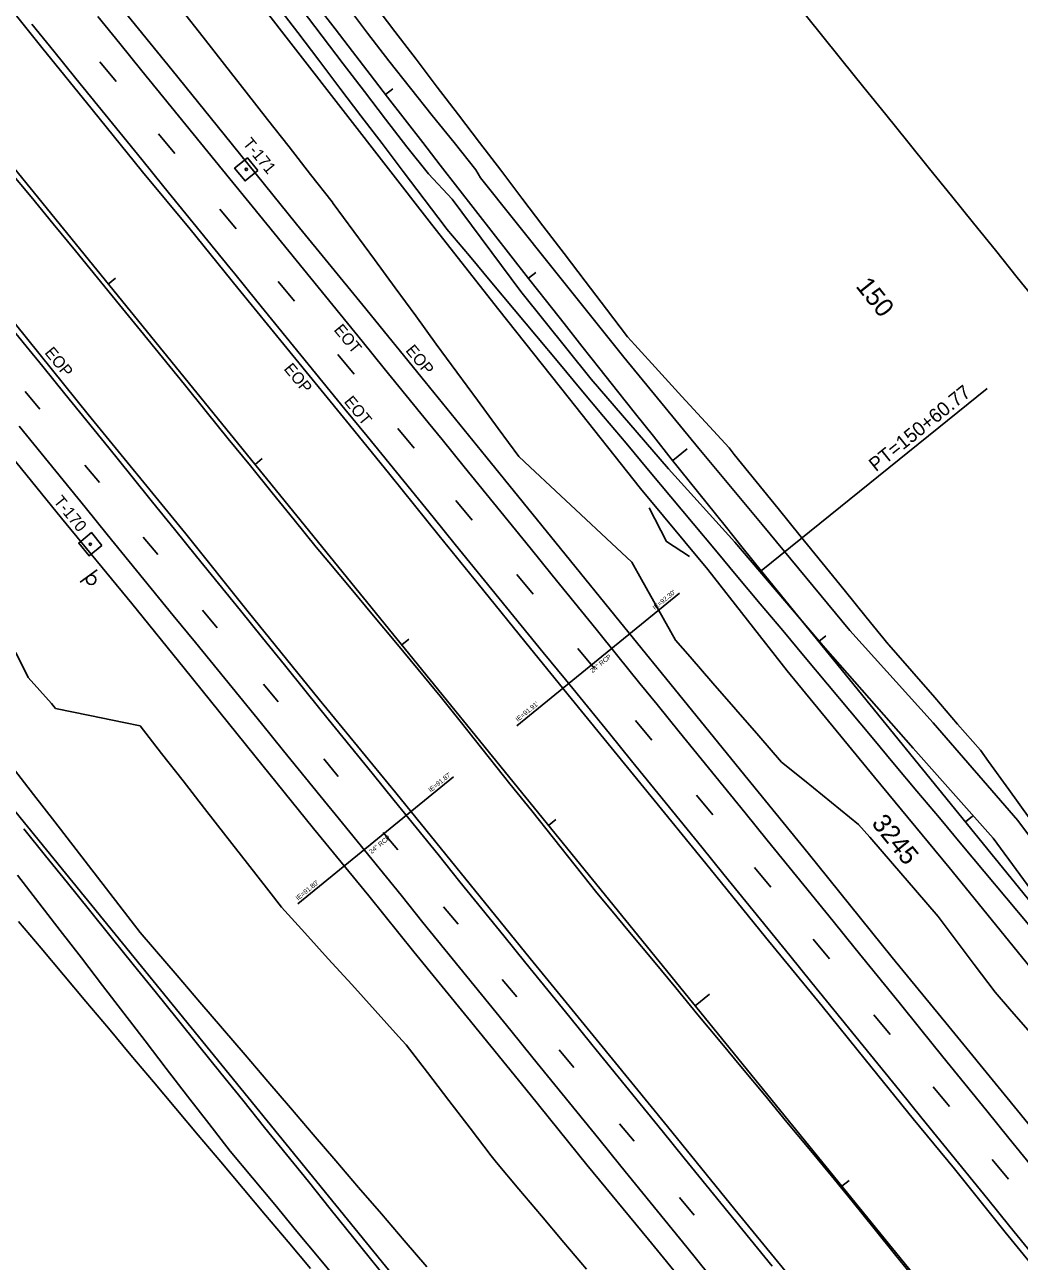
# Model space of a CAD drawing. Extents: x 2132221 to 2141942, y 535736 to 547298.
# Drawn here: x 2140262 to 2140690, y 537530 to 538062 of the extents above; entities that cross this region are included whole.
import ezdxf

# ---------------------------------------------------------------- set-up
doc = ezdxf.new("R2010")
doc.units = 0
for name, color, linetype in [('RD_EX_BldgApp', 7, 'Continuous'), ('RD_EX_DR_Inlet_txCode', 7, 'Continuous'), ('RD_EX_DR_Pipe', 7, 'Continuous'), ('RD_EX_DR_Pipe_txCode', 7, 'Continuous'), ('RD_EX_Driveway', 7, 'Continuous'), ('RD_EX_Fence_Other', 7, 'Continuous'), ('RD_EX_GuardRail', 7, 'Continuous'), ('RD_EX_Misc', 7, 'Continuous'), ('RD_EX_Misc_txCode', 7, 'Continuous'), ('RD_EX_Road', 7, 'Continuous'), ('RD_EX_Road_txCode', 7, 'Continuous'), ('RD_EX_VEG', 7, 'Continuous'), ('RD_HC_Cl', 7, 'Continuous'), ('RD_HC_Data', 7, 'Continuous'), ('RD_HC_Data_Tic', 7, 'Continuous'), ('RD_HC_Survey', 7, 'Continuous'), ('RD_HC_Survey_txCode', 7, 'Continuous'), ('RD_HC_TX_Sta50', 7, 'Continuous'), ('TOPO_E_TLIML-Line', 7, 'Continuous')]:
    doc.layers.add(name, color=color, linetype=linetype)

msp = doc.modelspace()

# ---------------------------------------------------------------- linework, layer by layer
at = {"layer": 'RD_EX_BldgApp'}
msp.add_line((2140293.26, 537827.39), (2140285.95, 537822.14), dxfattribs=at)
msp.add_circle((2140290.77, 537823.11), 2, dxfattribs=at)
at = {"layer": 'RD_EX_DR_Pipe'}
for points in [[(2140473.68, 537760.27), (2140543.61, 537817.28)], [(2140446.58, 537738.36), (2140379.58, 537683.77)]]:
    msp.add_lwpolyline(points, dxfattribs=at)
at = {"layer": 'RD_EX_Driveway'}
for points in [[(2140380.95, 538068.73), (2140390.03, 538056.84), (2140399.12, 538044.94), (2140408.21, 538033.05), (2140417.29, 538021.16), (2140426.45, 538009.32), (2140435.8, 537997.63), (2140445.93, 537986.7)], [(2140458.06, 537995.95), (2140456.14, 537999.39), (2140446.75, 538011.09), (2140437.36, 538022.79), (2140427.97, 538034.48), (2140418.66, 538046.24), (2140409.58, 538058.18), (2140400.51, 538070.13)], [(2140458.06, 537995.95), (2140488.23, 537958.18), (2140519.81, 537918.83), (2140552.04, 537879.57), (2140579.22, 537846.81), (2140616.97, 537801.32), (2140652.79, 537761.62), (2140689.12, 537719.55), (2140720.75, 537677.36)], [(2140445.93, 537986.7), (2140475.53, 537947), (2140505.71, 537909.4), (2140538.89, 537870.87), (2140567.54, 537839.33), (2140606.35, 537793.62), (2140644.19, 537750.74), (2140678.5, 537711.95), (2140709.72, 537669.37)], [(2140261.73, 537716.06), (2140271.14, 537704.38), (2140280.56, 537692.71), (2140289.98, 537681.03), (2140299.39, 537669.36), (2140308.81, 537657.68), (2140318.22, 537646.01), (2140327.64, 537634.34), (2140337.05, 537622.66), (2140346.47, 537610.99), (2140355.89, 537599.31), (2140365.3, 537587.64), (2140384.13, 537564.29), (2140393.55, 537552.62), (2140431.21, 537505.92)], [(2140398.38, 537519.84), (2140388.8, 537531.36), (2140379.22, 537542.87), (2140369.64, 537554.39), (2140360.06, 537565.9), (2140350.49, 537577.42), (2140341.27, 537589.22), (2140332.14, 537601.1), (2140323.02, 537612.97), (2140313.89, 537624.85), (2140304.76, 537636.72), (2140295.63, 537648.6), (2140286.5, 537660.47), (2140277.37, 537672.35), (2140268.25, 537684.22), (2140259.12, 537696.1)]]:
    msp.add_lwpolyline(points, dxfattribs=at)
at = {"layer": 'RD_EX_Fence_Other'}
for p, q in [((2140437.03, 537975.97), (2140347.96, 538090.82)), ((2140167.14, 537835.13), (2140668.17, 537219.94))]:
    msp.add_line(p, q, dxfattribs=at)
msp.add_lwpolyline([(2140437.03, 537975.97), (2140466.04, 537939.25), (2140495.76, 537901.58), (2140526.85, 537862.32), (2140555.79, 537827.47), (2140590, 537783.88), (2140627.49, 537738.23), (2140659.68, 537699.4), (2140694.45, 537656.5)], dxfattribs=at)
at = {"layer": 'RD_EX_GuardRail'}
msp.add_lwpolyline([(2140646.18, 537520.88), (2140636.74, 537532.54), (2140627.31, 537544.2), (2140617.87, 537555.86), (2140609.03, 537566.78), (2140599.46, 537578.33), (2140589.89, 537589.88), (2140580.32, 537601.44), (2140570.75, 537612.99), (2140561.18, 537624.54), (2140551.61, 537636.09), (2140542.04, 537647.64), (2140532.47, 537659.19), (2140522.91, 537670.74), (2140513.34, 537682.29), (2140508.19, 537688.5), (2140498.84, 537700.23), (2140489.5, 537711.96), (2140480.15, 537723.69), (2140470.8, 537735.42), (2140468.06, 537738.86), (2140458.71, 537750.59), (2140449.36, 537762.32), (2140440.84, 537773.01), (2140431.26, 537784.55), (2140421.67, 537796.09), (2140412.09, 537807.63), (2140402.5, 537819.16), (2140392.91, 537830.7), (2140387.52, 537837.19), (2140378.07, 537848.84), (2140368.61, 537860.48), (2140359.16, 537872.13), (2140349.7, 537883.77), (2140340.24, 537895.42), (2140330.79, 537907.06), (2140321.33, 537918.71), (2140311.88, 537930.35), (2140302.96, 537941.33), (2140293.44, 537952.93), (2140283.93, 537964.52), (2140274.41, 537976.12), (2140264.89, 537987.71), (2140255.38, 537999.31)], dxfattribs=at)
at = {"layer": 'RD_EX_Misc'}
for p, q in [((2140294.42, 538045.81), (2140301.44, 538037.36)), ((2140319.66, 538014.91), (2140326.68, 538006.46)), ((2140346.01, 537982.5), (2140353.03, 537974.05)), ((2140371.16, 537951.35), (2140378.17, 537942.9)), ((2140396.75, 537919.93), (2140403.77, 537911.48)), ((2140262.38, 537904.03), (2140268.68, 537896.5)), ((2140422.62, 537888.2), (2140429.64, 537879.75)), ((2140288.01, 537872.4), (2140294.3, 537864.88)), ((2140447.58, 537857.2), (2140454.59, 537848.75)), ((2140313.03, 537841.43), (2140319.33, 537833.91)), ((2140473.81, 537825.33), (2140480.83, 537816.88)), ((2140338.66, 537809.99), (2140344.95, 537802.46)), ((2140499.91, 537793.53), (2140506.93, 537785.08)), ((2140364.82, 537778.18), (2140371.12, 537770.66)), ((2140524.7, 537762.56), (2140531.72, 537754.11)), ((2140390.69, 537746.08), (2140396.98, 537738.55)), ((2140551.05, 537730.53), (2140558.07, 537722.08)), ((2140416.31, 537714.45), (2140422.6, 537706.92)), ((2140575.89, 537699.38), (2140582.91, 537690.93)), ((2140442.17, 537682.52), (2140448.47, 537675)), ((2140601.1, 537668.53), (2140608.12, 537660.08)), ((2140467.5, 537651.26), (2140473.79, 537643.73)), ((2140627.26, 537636.07), (2140634.28, 537627.62)), ((2140491.99, 537620.95), (2140498.28, 537613.42)), ((2140652.77, 537605.04), (2140659.79, 537596.59)), ((2140517.85, 537589.2), (2140524.14, 537581.68)), ((2140678.05, 537573.86), (2140685.07, 537565.41)), ((2140543.71, 537557.46), (2140550.01, 537549.93))]:
    msp.add_line(p, q, dxfattribs=at)
for points in [[(2140265.2, 538061.99), (2140274.65, 538050.34), (2140284.11, 538038.7), (2140293.57, 538027.06), (2140303.03, 538015.42), (2140312.49, 538003.78), (2140321.95, 537992.14), (2140331.41, 537980.5), (2140340.87, 537968.86), (2140350.33, 537957.22), (2140352.46, 537954.6), (2140361.94, 537942.97), (2140371.41, 537931.35), (2140380.89, 537919.72), (2140390.37, 537908.09), (2140399.84, 537896.46), (2140409.32, 537884.84), (2140418.8, 537873.21), (2140428.27, 537861.58), (2140437.75, 537849.96), (2140447.23, 537838.33), (2140456.7, 537826.7), (2140466.18, 537815.07), (2140475.66, 537803.45), (2140485.13, 537791.82), (2140494.61, 537780.19), (2140504.09, 537768.57), (2140513.57, 537756.94), (2140523.04, 537745.31), (2140524.93, 537742.99), (2140534.39, 537731.35), (2140543.84, 537719.71), (2140553.3, 537708.07), (2140562.76, 537696.42), (2140572.22, 537684.78), (2140581.67, 537673.14), (2140591.13, 537661.49), (2140600.59, 537649.85), (2140610.04, 537638.21), (2140619.5, 537626.56), (2140628.96, 537614.92), (2140638.41, 537603.28), (2140647.87, 537591.63), (2140657.33, 537579.99), (2140666.79, 537568.35), (2140676.24, 537556.7), (2140685.7, 537545.06), (2140695.16, 537533.42)], [(2140293.61, 538065.27), (2140303.08, 538053.64), (2140312.54, 538042), (2140322.01, 538030.37), (2140331.48, 538018.73), (2140340.95, 538007.1), (2140350.41, 537995.46), (2140359.88, 537983.83), (2140369.35, 537972.19), (2140378.81, 537960.56), (2140388.28, 537948.92), (2140397.75, 537937.29), (2140407.21, 537925.65), (2140416.68, 537914.02), (2140426.15, 537902.38), (2140435.61, 537890.75), (2140441.62, 537883.36), (2140451.07, 537871.72), (2140460.52, 537860.07), (2140469.97, 537848.42), (2140479.43, 537836.77), (2140488.88, 537825.13), (2140498.33, 537813.48), (2140507.78, 537801.83), (2140517.23, 537790.18), (2140526.68, 537778.54), (2140534.09, 537769.41), (2140543.54, 537757.76), (2140552.99, 537746.11), (2140562.44, 537734.47), (2140571.89, 537722.82), (2140581.35, 537711.17), (2140590.8, 537699.52), (2140600.25, 537687.88), (2140609.7, 537676.23), (2140619.15, 537664.58), (2140628.6, 537652.93), (2140638.06, 537641.28), (2140647.51, 537629.64), (2140656.96, 537617.99), (2140666.41, 537606.34), (2140675.86, 537594.69), (2140685.31, 537583.05), (2140694.76, 537571.4)], [(2140253.28, 537935.2), (2140262.76, 537923.58), (2140269.95, 537914.76), (2140279.39, 537903.1), (2140288.83, 537891.45), (2140298.27, 537879.79), (2140307.71, 537868.13), (2140317.15, 537856.47), (2140326.59, 537844.81), (2140336.02, 537833.16), (2140345.46, 537821.5), (2140354.9, 537809.84), (2140364.34, 537798.18), (2140373.78, 537786.52), (2140383.22, 537774.87), (2140392.66, 537763.21), (2140402.1, 537751.55), (2140411.54, 537739.89), (2140420.97, 537728.23), (2140430.41, 537716.58), (2140439.85, 537704.92), (2140449.29, 537693.26), (2140458.73, 537681.6), (2140468.17, 537669.94), (2140477.61, 537658.29), (2140487.05, 537646.63), (2140496.49, 537634.97), (2140505.92, 537623.31), (2140507.8, 537621), (2140517.26, 537609.36), (2140526.72, 537597.72), (2140536.18, 537586.08), (2140545.64, 537574.44), (2140555.1, 537562.8), (2140564.56, 537551.16), (2140574.02, 537539.52), (2140583.48, 537527.88)], [(2140556.3, 537524.4), (2140546.84, 537536.04), (2140537.39, 537547.69), (2140527.94, 537559.33), (2140518.48, 537570.98), (2140509.03, 537582.63), (2140499.57, 537594.27), (2140490.12, 537605.92), (2140480.66, 537617.56), (2140471.21, 537629.21), (2140461.76, 537640.85), (2140452.3, 537652.5), (2140442.85, 537664.14), (2140433.39, 537675.79), (2140423.94, 537687.43), (2140414.48, 537699.08), (2140405.03, 537710.73), (2140395.58, 537722.37), (2140392.36, 537726.34), (2140382.88, 537737.97), (2140373.41, 537749.6), (2140363.94, 537761.23), (2140354.47, 537772.86), (2140344.99, 537784.49), (2140335.52, 537796.12), (2140326.05, 537807.75), (2140316.57, 537819.38), (2140307.1, 537831.01), (2140297.63, 537842.64), (2140288.16, 537854.27), (2140278.68, 537865.9), (2140269.21, 537877.53), (2140259.74, 537889.16)]]:
    msp.add_lwpolyline(points, dxfattribs=at)
at = {"layer": 'RD_EX_Road'}
for points in [[(2139949.7, 538504.1), (2139971.57, 538477.21), (2139993.77, 538449.7), (2140019.28, 538418.71), (2140043.62, 538388.82), (2140070.61, 538355.67), (2140097.3, 538322.85), (2140125.56, 538288.11), (2140151.73, 538255.95), (2140176.45, 538225.34), (2140199.21, 538197.53), (2140224.25, 538166.52), (2140246.97, 538138.6), (2140274.95, 538104.46), (2140301.56, 538071.66), (2140325.51, 538042.29), (2140347.94, 538014.52), (2140379.07, 537976.03), (2140407.52, 537941.15), (2140434.36, 537908.22)], [(2139921.79, 538480), (2139946.02, 538450.34), (2139974.1, 538415.49), (2139997.12, 538387.16), (2140017.9, 538361.65), (2140039.96, 538334.4), (2140063.9, 538304.87), (2140087.44, 538275.84), (2140111.59, 538246.38), (2140136.82, 538215.31), (2140158.07, 538189.6), (2140178.39, 538164.11), (2140199.95, 538138.01), (2140232.94, 538097.16), (2140248.09, 538078.69), (2140269.53, 538052.05), (2140291.12, 538025.3), (2140312.85, 537998.52), (2140333.22, 537973.82), (2140353.82, 537948.47), (2140374.86, 537922.74), (2140401.79, 537889.76)], [(2139857.97, 538425.22), (2139881.25, 538396.49), (2139906.86, 538364.69), (2139936.98, 538327.43), (2139965.41, 538293.27), (2139992.83, 538259.43), (2140029.94, 538213.8), (2140070.83, 538163.2), (2140102.23, 538124.59), (2140136.12, 538082.6), (2140166.33, 538045.8), (2140194.75, 538011.29), (2140224.05, 537974.8), (2140258.2, 537933.02), (2140289.5, 537894.16), (2140331.4, 537842.81)], [(2139821.34, 538407.52), (2139844.07, 538380.28), (2139869.36, 538350.15), (2139893.18, 538321.68), (2139922.97, 538286.25), (2139948.19, 538255.39), (2139971.24, 538227.13), (2139997.6, 538194.42), (2140020.91, 538165.54), (2140045.38, 538135.86), (2140069.13, 538106.42), (2140093.97, 538075.81), (2140118.85, 538045.18), (2140147.52, 538010.04), (2140173.04, 537978.51), (2140202.74, 537942.39), (2140230.85, 537907.67), (2140252.16, 537881.37), (2140277.92, 537849.66), (2140308.18, 537812.91)], [(2140434.36, 537908.22), (2140460.47, 537876.18), (2140492.53, 537836.57), (2140520.2, 537802.5), (2140543.28, 537774.11), (2140569.92, 537741.29), (2140598.99, 537705.58), (2140635.15, 537660.72), (2140659.49, 537631.01), (2140683.25, 537601.85), (2140709.35, 537569.9), (2140732.09, 537542.02), (2140755.87, 537512.58), (2140779.68, 537483.3), (2140808.24, 537448.04), (2140833.52, 537417.03), (2140853.95, 537391.97), (2140884.7, 537353.95), (2140918.19, 537312.33)], [(2140401.79, 537889.76), (2140419.1, 537868.31), (2140440.28, 537842.06), (2140457.07, 537821.41), (2140479.63, 537793.5), (2140497.07, 537772.06), (2140528.29, 537733.78), (2140556.9, 537698.73), (2140580.71, 537669.45), (2140604.99, 537639.72), (2140623.48, 537616.74), (2140644.19, 537591.33), (2140661.9, 537569.77), (2140683.67, 537542.61), (2140702.49, 537519.59), (2140728.69, 537487.42), (2140749.87, 537461.7), (2140775.36, 537430.65), (2140800.43, 537399.52), (2140820.18, 537375.08), (2140845.19, 537344.29), (2140878.48, 537303.34)], [(2140331.4, 537842.81), (2140358.28, 537809.38), (2140388.82, 537771.67), (2140421.69, 537731.51), (2140479.51, 537660.25), (2140507.86, 537625.51), (2140538.58, 537587.96), (2140567.51, 537552.3), (2140601.53, 537510.68), (2140627.83, 537478.02), (2140656.06, 537443.32), (2140673.61, 537421.48), (2140693.03, 537398.17), (2140727.01, 537356.12), (2140758.56, 537317.28), (2140783, 537287.03), (2140817.12, 537245.45)], [(2140308.18, 537812.91), (2140330.69, 537785.06), (2140361.03, 537747.33), (2140386.29, 537716.18), (2140410.14, 537687.23), (2140429.5, 537663.09), (2140452.46, 537634.85), (2140479.43, 537601.73), (2140503.83, 537571.58), (2140530.32, 537539.38), (2140563.72, 537498.51), (2140596.15, 537458.64), (2140622.21, 537426.62), (2140652.24, 537389.59), (2140680.61, 537354.53), (2140712.38, 537315.48), (2140743.36, 537277.44), (2140765.02, 537250.67), (2140795.61, 537213.06)]]:
    msp.add_lwpolyline(points, dxfattribs=at)
at = {"layer": 'RD_EX_VEG'}
for points in [[(2140694.03, 537720.68), (2140685.25, 537732.85), (2140676.48, 537745.02), (2140673.06, 537749.76), (2140663.23, 537761.08), (2140653.39, 537772.41), (2140643.56, 537783.73), (2140633.72, 537795.06), (2140633.39, 537795.44), (2140623.94, 537807.09), (2140614.49, 537818.74), (2140605.04, 537830.39), (2140595.59, 537842.04), (2140586.14, 537853.69), (2140576.69, 537865.34), (2140567.24, 537876.99), (2140564.98, 537879.78), (2140554.86, 537890.85), (2140544.75, 537901.93), (2140534.63, 537913), (2140524.52, 537924.08), (2140521.33, 537927.57), (2140512.24, 537939.5), (2140503.15, 537951.44), (2140494.06, 537963.37), (2140484.97, 537975.3), (2140475.88, 537987.23), (2140466.8, 537999.17), (2140457.71, 538011.1), (2140448.62, 538023.03), (2140439.53, 538034.97), (2140430.44, 538046.9), (2140421.35, 538058.83), (2140412.26, 538070.76)], [(2140695.38, 537627.29), (2140685.58, 537638.65), (2140679.46, 537645.75), (2140670.44, 537657.72), (2140661.41, 537669.7), (2140654.89, 537678.35), (2140645.08, 537689.69), (2140635.27, 537701.04), (2140625.46, 537712.39), (2140620.7, 537717.89), (2140609.03, 537727.31), (2140597.36, 537736.73), (2140587.58, 537744.62), (2140577.75, 537755.94), (2140567.91, 537767.27), (2140558.07, 537778.59), (2140548.24, 537789.91), (2140542.02, 537797.07), (2140534.7, 537810.16), (2140527.37, 537823.24), (2140523.21, 537830.66), (2140512.26, 537840.9), (2140501.3, 537851.14), (2140490.34, 537861.39), (2140479.38, 537871.63), (2140474.6, 537876.09), (2140465.73, 537888.18), (2140456.86, 537900.28), (2140447.99, 537912.37), (2140439.12, 537924.47), (2140430.25, 537936.56), (2140421.37, 537948.66), (2140412.5, 537960.76), (2140403.63, 537972.85), (2140394.76, 537984.95), (2140394.29, 537985.58), (2140385.05, 537997.4), (2140375.81, 538009.21), (2140366.57, 538021.03), (2140357.33, 538032.84), (2140348.09, 538044.66), (2140338.85, 538056.48), (2140329.92, 538067.89)], [(2140370.45, 538070.4), (2140379.51, 538058.45), (2140388.58, 538046.5), (2140397.65, 538034.55), (2140406.72, 538022.6), (2140415.78, 538010.65), (2140424.85, 537998.7), (2140433.92, 537986.75), (2140442.99, 537974.8), (2140443.71, 537973.85), (2140453.33, 537962.35), (2140462.95, 537950.84), (2140472.58, 537939.33), (2140482.2, 537927.83), (2140491.82, 537916.32), (2140501.44, 537904.81), (2140511.07, 537893.3), (2140520.69, 537881.8), (2140530.31, 537870.29), (2140539.93, 537858.78), (2140549.56, 537847.28), (2140559.18, 537835.77), (2140568.8, 537824.26), (2140578.42, 537812.76), (2140588.05, 537801.25), (2140597.67, 537789.74), (2140607.29, 537778.24), (2140616.91, 537766.73), (2140626.54, 537755.22), (2140636.16, 537743.72), (2140645.78, 537732.21), (2140655.4, 537720.7), (2140665.03, 537709.19), (2140674.65, 537697.69), (2140684.27, 537686.18), (2140693.89, 537674.67)], [(2140530.68, 537854.02), (2140538.08, 537839.53), (2140547.93, 537833.12)], [(2140258.31, 537791.77), (2140263.71, 537781.12), (2140273.61, 537769.85), (2140275.46, 537767.75), (2140290.15, 537764.73), (2140304.84, 537761.7), (2140311.78, 537760.27), (2140321.01, 537748.44), (2140330.23, 537736.62), (2140339.46, 537724.79), (2140348.69, 537712.96), (2140357.91, 537701.14), (2140367.14, 537689.31), (2140372.55, 537682.38), (2140382.61, 537671.26), (2140392.68, 537660.13), (2140402.74, 537649.01), (2140412.81, 537637.89), (2140422.87, 537626.77), (2140426.23, 537623.05), (2140435.36, 537611.15), (2140444.49, 537599.25), (2140453.61, 537587.35), (2140462.74, 537575.44), (2140464.96, 537572.55), (2140474.63, 537561.09), (2140484.3, 537549.62), (2140493.98, 537538.16), (2140503.65, 537526.69)], [(2140435.01, 537527.63), (2140425.25, 537539.02), (2140415.49, 537550.41), (2140405.73, 537561.8), (2140395.97, 537573.19), (2140386.21, 537584.58), (2140376.45, 537595.97), (2140366.69, 537607.36), (2140356.93, 537618.75), (2140347.17, 537630.14), (2140337.41, 537641.53), (2140327.65, 537652.92), (2140317.89, 537664.31), (2140311.78, 537671.44), (2140302.61, 537683.31), (2140293.45, 537695.19), (2140284.28, 537707.06), (2140275.12, 537718.94), (2140265.95, 537730.81), (2140256.78, 537742.68)], [(2140259.54, 537676.14), (2140269.19, 537664.66), (2140278.85, 537653.18), (2140288.5, 537641.7), (2140298.16, 537630.22), (2140307.82, 537618.74), (2140317.47, 537607.26), (2140327.13, 537595.78), (2140336.78, 537584.3), (2140346.44, 537572.82), (2140356.09, 537561.34), (2140365.75, 537549.87), (2140375.4, 537538.39), (2140385.06, 537526.91)]]:
    msp.add_lwpolyline(points, dxfattribs=at)
at = {"layer": 'RD_HC_Cl'}
for p, q in [((2136971.61, 542041.65), (2141699.63, 536226.46)), ((2140578.77, 537826.98), (2141038.08, 537262.06))]:
    msp.add_line(p, q, dxfattribs=at)
msp.add_arc((2150022.65, 545440.3), 12130.51, 215.140721, 218.874533, dxfattribs=at)
at = {"layer": 'RD_HC_Data'}
msp.add_line((2140578.77, 537826.98), (2140676, 537905.36), dxfattribs=at)
at = {"layer": 'RD_HC_Data_Tic'}
for p, q in [((2140417.3, 538031.74), (2140420.47, 538034.18)), ((2140478.7, 537952.81), (2140481.85, 537955.28)), ((2140298.1, 537950.27), (2140301.2, 537952.79)), ((2140540.75, 537874.39), (2140547, 537879.38)), ((2140361.18, 537872.68), (2140364.29, 537875.2)), ((2140424.27, 537795.09), (2140427.37, 537797.61)), ((2140603.52, 537796.54), (2140606.62, 537799.06)), ((2140487.35, 537717.5), (2140490.46, 537720.02)), ((2140666.6, 537718.95), (2140669.71, 537721.47)), ((2140550.44, 537639.91), (2140556.64, 537644.95)), ((2140613.52, 537562.32), (2140616.63, 537564.84))]:
    msp.add_line(p, q, dxfattribs=at)
at = {"layer": 'RD_HC_Survey'}
for points in [[(2140362.35, 537999.06), (2140357.88, 538004.53), (2140352.41, 538000.06), (2140356.88, 537994.59)], [(2140295.33, 537837.91), (2140290.86, 537843.38), (2140285.39, 537838.91), (2140289.86, 537833.44)]]:
    msp.add_lwpolyline(points, close=True, dxfattribs=at)
for centre in [(2140357.38, 537999.56), (2140290.36, 537838.41)]:
    msp.add_circle(centre, 0.5, dxfattribs=at)
at = {"layer": 'TOPO_E_TLIML-Line'}
msp.add_lwpolyline([(2140698.33, 537941.44), (2140688.91, 537953.12), (2140679.49, 537964.79), (2140670.07, 537976.46), (2140660.65, 537988.14), (2140651.23, 537999.81), (2140641.81, 538011.48), (2140632.39, 538023.15), (2140622.97, 538034.83), (2140613.54, 538046.5), (2140604.12, 538058.17), (2140594.7, 538069.84)], dxfattribs=at)

# ---------------------------------------------------------------- texts
at = {"layer": 'RD_EX_DR_Inlet_txCode'}
for s, rotation, p in [("IE=92.30'", 39.1888, (2140533.13, 537810.03)), ("IE=91.91'", 39.1888, (2140474.21, 537761.99)), ("IE=91.87'", 39.1777, (2140436.71, 537731.61)), ("IE=91.80'", 39.1777, (2140379.67, 537685.13))]:
    msp.add_text(s, height=2, rotation=rotation, dxfattribs=at).set_placement(p)
at = {"layer": 'RD_EX_DR_Pipe_txCode'}
for rotation, p in [(39.1888, (2140506.32, 537782.94)), (39.1777, (2140411.31, 537705.16))]:
    msp.add_text('24" RCP', height=2, rotation=rotation, dxfattribs=at).set_placement(p)
at = {"layer": 'RD_EX_Misc_txCode'}
for p in [(2140394.81, 537930.48), (2140399.18, 537899.62)]:
    msp.add_text('EOT', height=5, rotation=309.5103, dxfattribs=at).set_placement(p)
at = {"layer": 'RD_EX_Road_txCode'}
for p in [(2140270.48, 537920.66), (2140425.65, 537921.62), (2140373.3, 537913.71)]:
    msp.add_text('EOP', height=5, rotation=309.5103, dxfattribs=at).set_placement(p)
at = {"layer": 'RD_HC_Data'}
msp.add_text('PT=150+60.77', height=6, rotation=38.8745, dxfattribs=at).set_placement((2140628.12, 537869.33))
at = {"layer": 'RD_HC_Survey_txCode'}
for s, p in [('T-171', (2140355.67, 538010.64)), ('T-170', (2140274.3, 537856.77))]:
    msp.add_text(s, height=5, rotation=309.2596, dxfattribs=at).set_placement(p)
at = {"layer": 'RD_HC_TX_Sta50'}
for s, rotation, p in [('150', 308.5875, (2140619.17, 537949.26)), ('3245', 309.1127, (2140625.94, 537718.24))]:
    msp.add_text(s, height=8, rotation=rotation, dxfattribs=at).set_placement(p)

doc.saveas('drawing.dxf')
